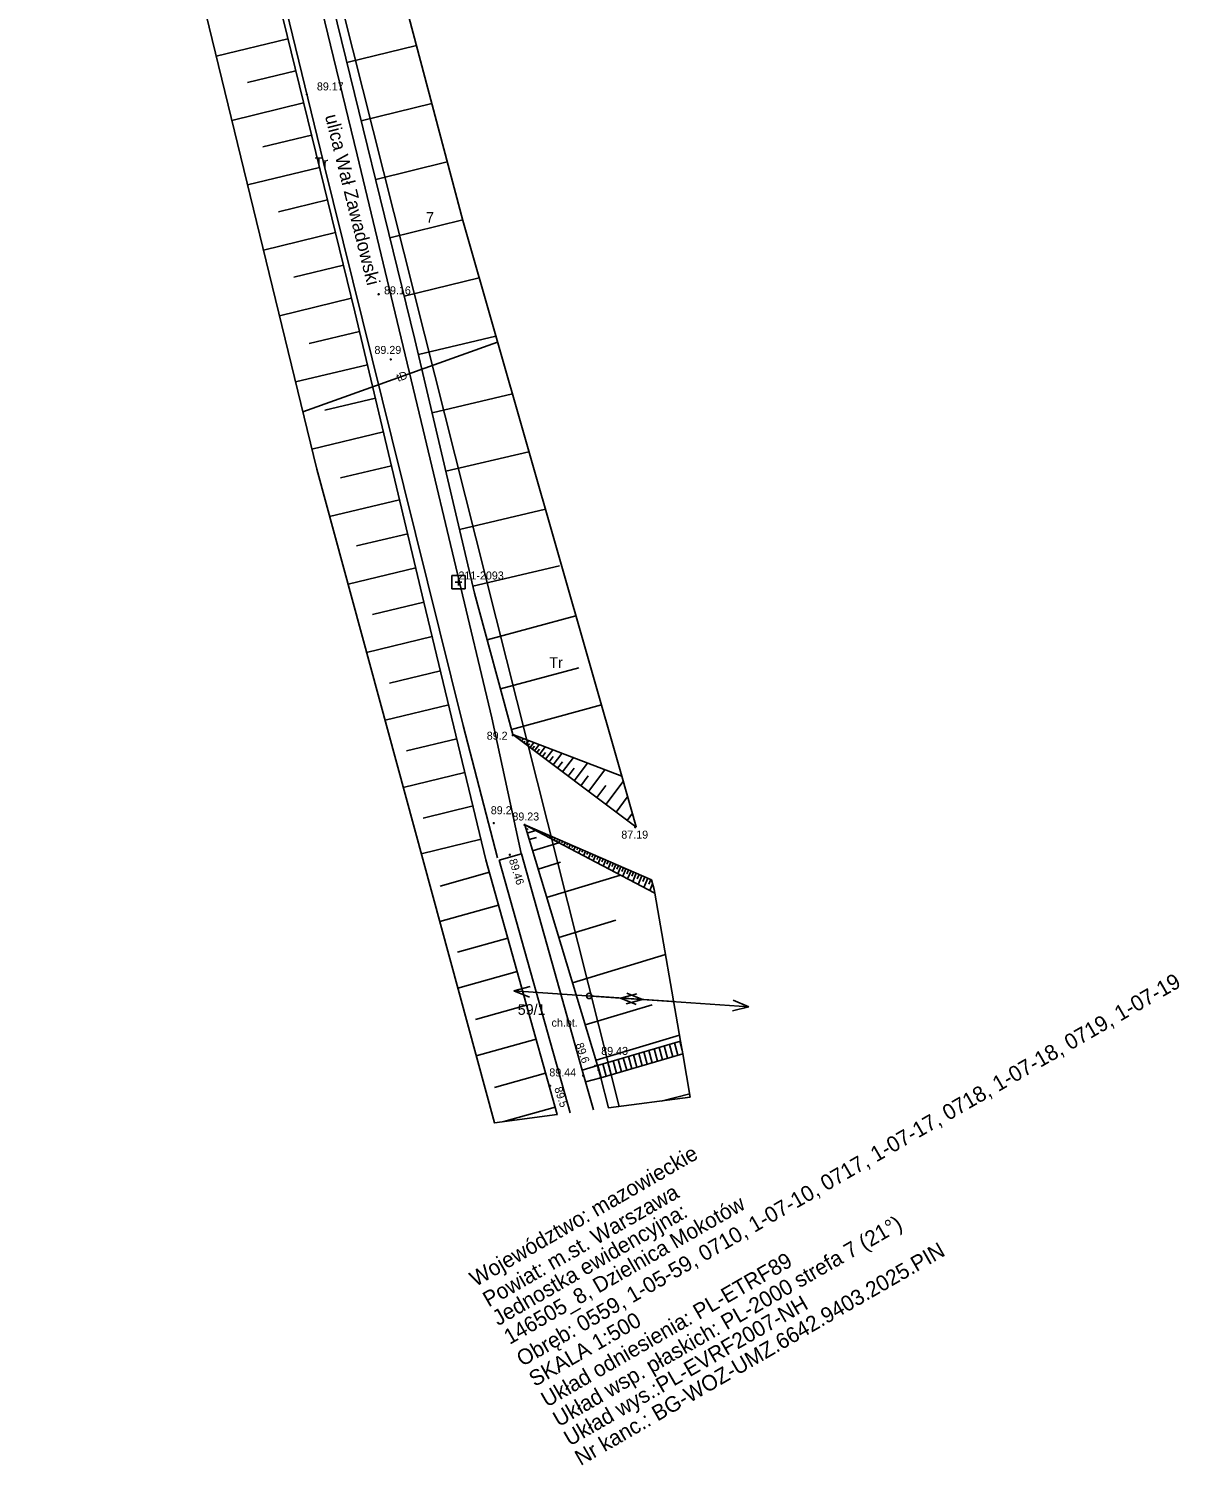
# Model space of a CAD drawing. Extents: x 7506075 to 7506993, y 5784375 to 5786367.
# Drawn here: x 7506884.8 to 7506992.6, y 5784374.7 to 5784509.3 of the extents above; entities that cross this region are included whole.
import ezdxf

# ---------------------------------------------------------------- set-up
doc = ezdxf.new("R2010")
doc.units = 0
for name, color, linetype in [('000 Inne (niezydentyfikowane)', 7, 'Continuous'), ('210-oznaczenie konturu użytku gruntowego', 7, 'Continuous'), ('211-numer działki ewidencyjnej', 7, 'Continuous'), ('216-obręb ewidencyjny', 7, 'Continuous'), ('218-kontur użytku gruntowego', 7, 'Continuous'), ('219-działka ewidencyjna', 7, 'Continuous'), ('994-Nazwa ulicy', 7, 'Continuous'), ('chodnik', 7, 'Continuous'), ('chodnik-Atr17', 7, 'Continuous'), ('jezdnia', 7, 'Continuous'), ('Pieczątka na wyrysie', 7, 'Continuous'), ('pikieta naturalna', 7, 'Continuous'), ('pikieta naturalna-Atr2', 7, 'Continuous'), ('pikieta sztuczna', 7, 'Continuous'), ('pikieta sztuczna-Atr2', 7, 'Continuous'), ('przewód elektroenergetyczny niskiego napięcia', 7, 'Continuous'), ('przewód telekomunikacyjny podziemny', 7, 'Continuous'), ('przewód telekomunikacyjny podziemny-Atr1', 7, 'Continuous'), ('schody w ciągu komunikacyjnym', 7, 'Continuous'), ('skarpa nieumocniona', 7, 'Continuous'), ('skarpa umocniona', 7, 'Continuous'), ('Szczegółowa osnowa geodezyjna pozioma', 7, 'Continuous'), ('Szczegółowa osnowa geodezyjna pozioma-Atr103', 7, 'Continuous'), ('słup przewodów napowietrznych', 7, 'Continuous')]:
    doc.layers.add(name, color=color, linetype=linetype)

# ---------------------------------------------------------------- blocks, each defined once
blk = doc.blocks.new('PW01')
blk.add_circle((0, 0), 0.045)
blk = doc.blocks.new('US15')
blk.add_circle((0, 0), 0.25)
blk = doc.blocks.new('SUEP1')
for p, q in [((0, 0), (5, 0)), ((5, 0), (3.5, 0.5)), ((5, 0), (3.5, -0.5)), ((5, 0), (15, 0)), ((15, 0), (13.5, 0.5)), ((15, 0), (13.5, -0.5))]:
    blk.add_line(p, q)
blk = doc.blocks.new('OSSP')
for p, q in [((-0.626, 0.625), (-0.626, -0.625)), ((-0.626, 0.625), (-0.626, -0.625)), ((0.624, 0.625), (-0.626, 0.625)), ((0.624, 0.625), (-0.626, 0.625)), ((0.3, 0), (-0.3, 0)), ((0.3, 0), (-0.3, 0)), ((0, -0.3), (0, 0.3)), ((0, -0.3), (0, 0.3)), ((0.624, -0.625), (0.624, 0.625)), ((0.624, -0.625), (0.624, 0.625)), ((-0.626, -0.625), (0.624, -0.625)), ((-0.626, -0.625), (0.624, -0.625))]:
    blk.add_line(p, q)

msp = doc.modelspace()

# ---------------------------------------------------------------- linework, layer by layer
at = {"layer": '000 Inne (niezydentyfikowane)'}
for p, q in [((7506909.13, 5784508.32), (7506902.413, 5784506.676)), ((7506914.66, 5784506.1), (7506921.166, 5784507.695)), ((7506909.87, 5784505.33), (7506905.35, 5784504.22)), ((7506910.6, 5784502.32), (7506903.874, 5784500.674)), ((7506916, 5784500.62), (7506922.611, 5784502.247)), ((7506911.34, 5784499.3), (7506906.79, 5784498.19)), ((7506912.08, 5784496.27), (7506905.346, 5784494.629)), ((7506917.35, 5784495.14), (7506924.059, 5784496.789)), ((7506912.82, 5784493.23), (7506908.23, 5784492.11)), ((7506913.57, 5784490.17), (7506906.831, 5784488.525)), ((7506918.69, 5784489.67), (7506925.502, 5784491.346)), ((7506914.32, 5784487.1), (7506909.68, 5784485.97)), ((7506920.03, 5784484.21), (7506927.048, 5784485.937)), ((7506915.08, 5784484.01), (7506908.331, 5784482.363)), ((7506915.83, 5784480.9), (7506911.13, 5784479.78)), ((7506921.36, 5784478.75), (7506928.615, 5784480.458)), ((7506916.57, 5784477.78), (7506909.837, 5784476.175)), ((7506917.32, 5784474.64), (7506912.58, 5784473.51)), ((7506922.64, 5784473.28), (7506930.162, 5784475.047)), ((7506918.07, 5784471.48), (7506911.37, 5784469.881)), ((7506923.93, 5784467.8), (7506931.71, 5784469.634)), ((7506918.83, 5784468.31), (7506914.05, 5784467.17)), ((7506919.59, 5784465.13), (7506913.032, 5784463.569)), ((7506925.21, 5784462.35), (7506933.252, 5784464.243)), ((7506920.35, 5784461.94), (7506915.54, 5784460.8)), ((7506921.11, 5784458.74), (7506914.757, 5784457.226)), ((7506926.46, 5784457.04), (7506934.58, 5784458.94)), ((7506921.87, 5784455.53), (7506917.04, 5784454.37)), ((7506927.8, 5784452.02), (7506936.106, 5784454.266)), ((7506922.65, 5784452.31), (7506916.495, 5784450.832)), ((7506923.42, 5784449.1), (7506918.64, 5784447.95)), ((7506929.05, 5784447.4), (7506936.4, 5784449.39)), ((7506924.19, 5784445.91), (7506918.224, 5784444.473)), ((7506930.07, 5784443.62), (7506938.497, 5784445.904)), ((7506924.95, 5784442.73), (7506920.23, 5784441.6)), ((7506930.42, 5784442.97), (7506930.44, 5784443.01)), ((7506930.62, 5784442.82), (7506930.71, 5784442.94)), ((7506930.82, 5784442.67), (7506930.89, 5784442.76)), ((7506931.02, 5784442.52), (7506931.2, 5784442.76)), ((7506931.22, 5784442.37), (7506931.33, 5784442.52)), ((7506931.42, 5784442.22), (7506931.69, 5784442.57)), ((7506931.62, 5784442.07), (7506931.78, 5784442.27)), ((7506931.82, 5784441.92), (7506932.17, 5784442.38)), ((7506932.02, 5784441.77), (7506932.22, 5784442.03)), ((7506932.23, 5784441.62), (7506932.66, 5784442.2)), ((7506932.45, 5784441.45), (7506932.69, 5784441.77)), ((7506932.7, 5784441.26), (7506933.23, 5784441.98)), ((7506932.97, 5784441.06), (7506933.27, 5784441.45)), ((7506933.27, 5784440.83), (7506933.94, 5784441.71)), ((7506933.61, 5784440.57), (7506933.98, 5784441.06)), ((7506933.99, 5784440.29), (7506934.8, 5784441.37)), ((7506934.4, 5784439.98), (7506934.86, 5784440.58)), ((7506934.87, 5784439.63), (7506935.87, 5784440.97)), ((7506935.95, 5784438.81), (7506937.19, 5784440.46)), ((7506925.71, 5784439.58), (7506919.933, 5784438.185)), ((7506935.38, 5784439.24), (7506935.94, 5784439.98)), ((7506936.58, 5784438.34), (7506937.27, 5784439.25)), ((7506937.28, 5784437.81), (7506938.81, 5784439.84)), ((7506938.06, 5784437.23), (7506938.91, 5784438.35)), ((7506938.92, 5784436.58), (7506940.547, 5784438.735)), ((7506926.47, 5784436.44), (7506921.8, 5784435.31)), ((7506939.87, 5784435.86), (7506940.91, 5784437.25)), ((7506940.9, 5784435.09), (7506941.4, 5784435.753)), ((7506931.33, 5784434.6), (7506931.41, 5784434.62)), ((7506931.44, 5784434.25), (7506931.65, 5784434.31)), ((7506931.54, 5784433.9), (7506932.32, 5784434.14)), ((7506931.77, 5784434.47), (7506931.75, 5784434.44)), ((7506932.01, 5784434.37), (7506932, 5784434.34)), ((7506932.24, 5784434.26), (7506932.21, 5784434.2)), ((7506932.48, 5784434.16), (7506932.46, 5784434.12)), ((7506932.72, 5784434.06), (7506932.67, 5784433.95)), ((7506932.96, 5784433.96), (7506932.93, 5784433.89)), ((7506933.2, 5784433.85), (7506933.14, 5784433.71)), ((7506933.43, 5784433.75), (7506933.4, 5784433.67)), ((7506933.67, 5784433.65), (7506933.6, 5784433.47)), ((7506927.22, 5784433.32), (7506921.623, 5784431.97)), ((7506931.73, 5784433.29), (7506932.43, 5784433.5)), ((7506932.04, 5784432.25), (7506934.51, 5784432.99)), ((7506933.91, 5784433.54), (7506933.87, 5784433.45)), ((7506934.15, 5784433.44), (7506934.06, 5784433.23)), ((7506934.39, 5784433.34), (7506934.34, 5784433.22)), ((7506934.62, 5784433.23), (7506934.52, 5784432.99)), ((7506934.86, 5784433.13), (7506934.8, 5784433)), ((7506935.1, 5784433.03), (7506934.98, 5784432.75)), ((7506935.34, 5784432.92), (7506935.27, 5784432.77)), ((7506935.58, 5784432.82), (7506935.44, 5784432.5)), ((7506935.81, 5784432.72), (7506935.74, 5784432.55)), ((7506936.05, 5784432.61), (7506935.9, 5784432.26)), ((7506936.29, 5784432.51), (7506936.21, 5784432.33)), ((7506936.53, 5784432.41), (7506936.36, 5784432.02)), ((7506936.76, 5784432.31), (7506936.68, 5784432.1)), ((7506932.57, 5784430.53), (7506934.67, 5784431.17)), ((7506937, 5784432.2), (7506936.82, 5784431.78)), ((7506937.24, 5784432.1), (7506937.14, 5784431.88)), ((7506937.48, 5784432), (7506937.28, 5784431.54)), ((7506937.72, 5784431.89), (7506937.61, 5784431.65)), ((7506937.95, 5784431.79), (7506937.74, 5784431.3)), ((7506938.19, 5784431.69), (7506938.08, 5784431.43)), ((7506938.43, 5784431.58), (7506938.2, 5784431.05)), ((7506938.67, 5784431.48), (7506938.55, 5784431.21)), ((7506938.91, 5784431.38), (7506938.66, 5784430.81)), ((7506939.14, 5784431.27), (7506939.02, 5784430.98)), ((7506939.38, 5784431.17), (7506939.12, 5784430.57)), ((7506939.62, 5784431.07), (7506939.49, 5784430.76)), ((7506939.86, 5784430.96), (7506939.58, 5784430.33)), ((7506928.01, 5784430.23), (7506923.4, 5784428.94)), ((7506933.37, 5784427.86), (7506940.29, 5784429.96)), ((7506940.1, 5784430.86), (7506939.95, 5784430.53)), ((7506940.33, 5784430.76), (7506940.04, 5784430.09)), ((7506940.57, 5784430.66), (7506940.42, 5784430.31)), ((7506940.8, 5784430.55), (7506940.5, 5784429.85)), ((7506941.04, 5784430.45), (7506940.88, 5784430.09)), ((7506941.28, 5784430.35), (7506940.96, 5784429.61)), ((7506941.52, 5784430.24), (7506941.36, 5784429.86)), ((7506941.77, 5784430.13), (7506941.44, 5784429.36)), ((7506942.03, 5784430.02), (7506941.86, 5784429.62)), ((7506942.3, 5784429.91), (7506941.94, 5784429.09)), ((7506942.57, 5784429.79), (7506942.38, 5784429.37)), ((7506942.84, 5784429.67), (7506942.47, 5784428.81)), ((7506943.13, 5784429.55), (7506942.94, 5784429.11)), ((7506943.294, 5784429.13), (7506943.03, 5784428.52)), ((7506928.87, 5784427.15), (7506923.352, 5784425.611)), ((7506934.51, 5784424.13), (7506939.86, 5784425.75)), ((7506929.73, 5784424.05), (7506925.03, 5784422.74)), ((7506935.79, 5784419.88), (7506944.502, 5784422.523)), ((7506930.61, 5784420.93), (7506925.048, 5784419.373)), ((7506931.49, 5784417.77), (7506926.71, 5784416.44)), ((7506936.99, 5784415.92), (7506943.25, 5784417.82)), ((7506938, 5784412.61), (7506945.815, 5784414.98)), ((7506932.38, 5784414.59), (7506926.773, 5784413.027)), ((7506933.27, 5784411.41), (7506928.48, 5784410.06)), ((7506944.09, 5784408.792), (7506946.772, 5784409.485)), ((7506934.17, 5784408.21), (7506929.37, 5784406.866))]:
    msp.add_line(p, q, dxfattribs=at)
at = {"layer": '216-obręb ewidencyjny'}
msp.add_lwpolyline([(7506940.165, 5784408.278), (7506895.02, 5784587.37)], dxfattribs=at)
at = {"layer": '218-kontur użytku gruntowego'}
msp.add_lwpolyline([(7506895.02, 5784587.37), (7506940.165, 5784408.278)], dxfattribs=at)
at = {"layer": '219-działka ewidencyjna'}
msp.add_lwpolyline([(7506940.165, 5784408.278), (7506895.02, 5784587.37)], dxfattribs=at)
msp.add_lwpolyline([(7506940.165, 5784408.278), (7506895.02, 5784587.37)], dxfattribs=at)
at = {"layer": 'chodnik'}
for points in [[(7506928.92, 5784431.37), (7506931, 5784431.95), (7506936.69, 5784411.7), (7506937.01, 5784410.6), (7506937.757, 5784407.963)], [(7506935.578, 5784407.678), (7506928.92, 5784431.37)]]:
    msp.add_lwpolyline(points, dxfattribs=at)
at = {"layer": 'jezdnia'}
for p, q in [((7506905.24, 5784526.442), (7506912.45, 5784496.722)), ((7506915.601, 5784497.452), (7506908.634, 5784526.274)), ((7506921.787, 5784471.676), (7506915.601, 5784497.452)), ((7506912.45, 5784496.722), (7506918.863, 5784470.905)), ((7506928.248, 5784444.705), (7506921.787, 5784471.676)), ((7506918.863, 5784470.905), (7506925.532, 5784443.966)), ((7506930.991, 5784431.972), (7506928.248, 5784444.705)), ((7506925.532, 5784443.966), (7506928.774, 5784431.568))]:
    msp.add_line(p, q, dxfattribs=at)
at = {"layer": 'przewód elektroenergetyczny niskiego napięcia'}
msp.add_lwpolyline([(7506937.35, 5784418.64), (7506945.27, 5784418.108)], dxfattribs=at)
at = {"layer": 'przewód telekomunikacyjny podziemny'}
msp.add_lwpolyline([(7506928.773, 5784479.905), (7506910.52, 5784473.372)], dxfattribs=at)
at = {"layer": 'schody w ciągu komunikacyjnym'}
for points in [[(7506946.12, 5784413.22), (7506938.45, 5784410.97), (7506938.14, 5784412.13), (7506945.92, 5784414.4)], [(7506936.69, 5784411.7), (7506938.14, 5784412.13), (7506938.45, 5784410.97), (7506937.01, 5784410.6)]]:
    msp.add_lwpolyline(points, close=True, dxfattribs=at)
for points in [[(7506942.955, 5784413.535), (7506943.269, 5784412.384)], [(7506943.435, 5784413.675), (7506943.749, 5784412.524)], [(7506943.915, 5784413.815), (7506944.228, 5784412.665)], [(7506944.395, 5784413.955), (7506944.708, 5784412.806)], [(7506944.875, 5784414.095), (7506945.188, 5784412.947)], [(7506945.355, 5784414.235), (7506945.668, 5784413.087)], [(7506945.835, 5784414.375), (7506946.07, 5784413.512)], [(7506938.154, 5784412.134), (7506938.47, 5784410.976)], [(7506938.634, 5784412.274), (7506938.95, 5784411.117)], [(7506939.114, 5784412.414), (7506939.43, 5784411.257)], [(7506939.594, 5784412.554), (7506939.91, 5784411.398)], [(7506940.074, 5784412.694), (7506940.389, 5784411.539)], [(7506940.554, 5784412.834), (7506940.869, 5784411.68)], [(7506941.034, 5784412.975), (7506941.349, 5784411.82)], [(7506941.515, 5784413.115), (7506941.829, 5784411.961)], [(7506941.995, 5784413.255), (7506942.309, 5784412.102)], [(7506942.475, 5784413.395), (7506942.789, 5784412.243)]]:
    msp.add_lwpolyline(points, dxfattribs=at)
at = {"layer": 'skarpa nieumocniona'}
for points in [[(7506940.41, 5784439.23), (7506941.76, 5784434.5), (7506941.59, 5784434.57), (7506930.2, 5784443.14)], [(7506943.18, 5784429.52), (7506943.44, 5784428.62), (7506943.5, 5784428.27), (7506931.31, 5784434.67)]]:
    msp.add_lwpolyline(points, close=True, dxfattribs=at)
at = {"layer": 'skarpa umocniona'}
for points in [[(7506900.61, 5784585.19), (7506925.52, 5784491.28), (7506940.41, 5784439.23), (7506930.2, 5784443.14), (7506926.62, 5784456.37), (7506921.03, 5784480.14), (7506904.83, 5784546.14), (7506896.52, 5784579.73), (7506894.51, 5784588.16), (7506891.56, 5784599.59), (7506896.29, 5784600.62)], [(7506900.61, 5784585.19), (7506925.52, 5784491.28), (7506940.41, 5784439.23), (7506930.2, 5784443.14), (7506926.62, 5784456.37), (7506921.03, 5784480.14), (7506904.83, 5784546.14), (7506896.52, 5784579.73), (7506894.51, 5784588.16), (7506891.56, 5784599.59), (7506896.29, 5784600.62)], [(7506900.96, 5784541.67), (7506905.19, 5784524.45), (7506912.52, 5784494.47), (7506915.39, 5784482.73), (7506921.87, 5784455.55), (7506927.68, 5784431.4), (7506934.36, 5784407.52), (7506928.48, 5784406.75), (7506911.83, 5784467.99), (7506886.29, 5784572.91), (7506884.84, 5784578.76), (7506891.3, 5784580.84)], [(7506900.96, 5784541.67), (7506905.19, 5784524.45), (7506912.52, 5784494.47), (7506915.39, 5784482.73), (7506921.87, 5784455.55), (7506927.68, 5784431.4), (7506934.36, 5784407.52), (7506928.48, 5784406.75), (7506911.83, 5784467.99), (7506886.29, 5784572.91), (7506884.84, 5784578.76), (7506891.3, 5784580.84)], [(7506943.5, 5784428.27), (7506945.92, 5784414.4), (7506938.14, 5784412.13), (7506931.31, 5784434.67)], [(7506943.5, 5784428.27), (7506945.92, 5784414.4), (7506938.14, 5784412.13), (7506931.31, 5784434.67)], [(7506946.83, 5784409.15), (7506939.18, 5784408.15), (7506938.45, 5784410.97), (7506946.12, 5784413.22)], [(7506946.83, 5784409.15), (7506939.18, 5784408.15), (7506938.45, 5784410.97), (7506946.12, 5784413.22)]]:
    msp.add_lwpolyline(points, close=True, dxfattribs=at)

# ---------------------------------------------------------------- block references
at = {"layer": 'pikieta naturalna'}
for p in [(7506930.2, 5784443.07), (7506928.41, 5784434.84), (7506937.91, 5784412.08), (7506933.69, 5784410.22)]:
    msp.add_blockref('PW01', p, dxfattribs=at)
at = {"layer": 'pikieta sztuczna'}
for p in [(7506910.9, 5784503.1), (7506917.63, 5784484.38), (7506918.76, 5784478.28), (7506931.31, 5784434.67), (7506941.67, 5784434.44), (7506929.92, 5784431.87), (7506936.78, 5784411.18), (7506938.22, 5784411.71)]:
    msp.add_blockref('PW01', p, dxfattribs=at)
at = {"layer": 'przewód elektroenergetyczny niskiego napięcia'}
for p, rotation in [((7506945.27, 5784418.108), 176.157), ((7506937.35, 5784418.64), -3.8430000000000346)]:
    msp.add_blockref('SUEP1', p, dxfattribs=dict(at, rotation=rotation))
at = {"layer": 'Szczegółowa osnowa geodezyjna pozioma'}
msp.add_blockref('OSSP', (7506925.11, 5784457.41), dxfattribs=at)
at = {"layer": 'słup przewodów napowietrznych'}
msp.add_blockref('US15', (7506937.35, 5784418.64), dxfattribs=at)

# ---------------------------------------------------------------- texts
at = {"layer": '210-oznaczenie konturu użytku gruntowego'}
for p in [(7506911.64, 5784496.2), (7506933.63, 5784449.38)]:
    msp.add_text('Tr', height=1, dxfattribs=at).set_placement(p)
at = {"layer": '211-numer działki ewidencyjnej'}
for s, p in [('7', (7506922.073, 5784491.08)), ('59/1', (7506930.66, 5784416.87))]:
    msp.add_text(s, height=1, dxfattribs=at).set_placement(p)
at = {"layer": '994-Nazwa ulicy'}
msp.add_text('ulica Wał Zawadowski', height=1.25, rotation=284.003, dxfattribs=at).set_placement((7506912.59, 5784501.08))
at = {"layer": 'chodnik-Atr17'}
msp.add_text('ch.bt.', height=0.75, dxfattribs=at).set_placement((7506933.83, 5784415.762))
msp.add_text('ch.bt.', height=0.75, dxfattribs=at).set_placement((7506933.83, 5784415.762))
at = {"layer": 'Pieczątka na wyrysie'}
for s, height, p in [('Obręb: 0559, 1-05-59, 0710, 1-07-10, 0717, 1-07-17, 0718, 1-07-18, 0719, 1-07-19', 1.455, (7506931.09, 5784383.88)), ('Województwo: mazowieckie', 1.455, (7506926.71, 5784391.36)), ('Powiat: m.st. Warszawa', 1.455, (7506927.93, 5784389.45)), ('Jednostka ewidencyjna: ', 1.455, (7506928.82, 5784387.69)), ('146505_8, Dzielnica Mokotów', 1.437, (7506929.9, 5784385.94)), ('Układ wsp. płaskich: PL-2000 strefa 7 (21°)', 1.455, (7506934.5, 5784378.22)), ('Nr kanc.: BG-WOZ-UMZ.6642.9403.2025.PIN', 1.455, (7506936.55, 5784374.59)), ('Układ odniesienia: PL-ETRF89', 1.455, (7506933.39, 5784380.06)), ('Układ wys.:PL-EVRF2007-NH ', 1.455, (7506935.53, 5784376.42)), ('SKALA 1:500', 1.455, (7506932.25, 5784381.99))]:
    msp.add_text(s, height=height, rotation=30, dxfattribs=at).set_placement(p)
at = {"layer": 'pikieta naturalna-Atr2'}
for p in [(7506927.756, 5784442.648), (7506928.134, 5784435.665)]:
    msp.add_text('89.2', height=0.75, dxfattribs=at).set_placement(p)
for s, rotation, p in [('89.6', 289.398, (7506936.066, 5784414.105)), ('89.5', 287.864, (7506934.072, 5784409.98))]:
    msp.add_text(s, height=0.75, rotation=rotation, dxfattribs=at).set_placement(p)
at = {"layer": 'pikieta sztuczna-Atr2'}
for s, p in [('89.17', (7506911.842, 5784503.479)), ('89.16', (7506918.133, 5784484.376)), ('89.29', (7506917.234, 5784478.792)), ('89.23', (7506930.159, 5784435.079)), ('87.19', (7506940.367, 5784433.38)), ('89.43', (7506938.483, 5784413.118)), ('89.44', (7506933.622, 5784411.101))]:
    msp.add_text(s, height=0.75, dxfattribs=at).set_placement(p)
msp.add_text('89.46', height=0.75, rotation=287.372, dxfattribs=at).set_placement((7506929.824, 5784431.367))
at = {"layer": 'przewód telekomunikacyjny podziemny-Atr1'}
msp.add_text('tD', height=0.75, rotation=19.693, dxfattribs=at).set_placement((7506919.458, 5784476.174))
at = {"layer": 'Szczegółowa osnowa geodezyjna pozioma-Atr103'}
msp.add_text('211-2093', height=0.75, dxfattribs=at).set_placement((7506925.11, 5784457.66))

doc.saveas('drawing.dxf')
